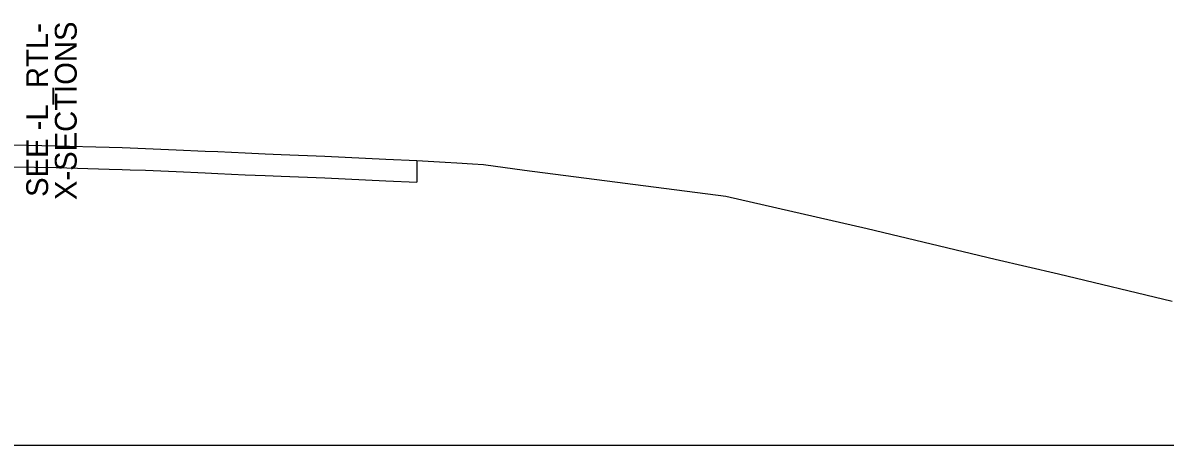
# Model space of a CAD drawing. Extents: x 2207892 to 2209721, y 61220 to 65449.
# Drawn here: x 2208142.1 to 2208194.4, y 62407.3 to 62426.6 of the extents above; entities that cross this region are included whole.
import ezdxf

# ---------------------------------------------------------------- set-up
doc = ezdxf.new("R2010")
doc.units = 0
for name, color, linetype in [('Exist DTM Breakline Cogo Elevation', 7, 'Continuous'), ('Exist DTM Drainline Cogo Comment', 7, 'Continuous'), ('Exist Roads EOP Other Cogo Elevation', 7, 'Continuous'), ('Exist Roads EOP Other Cogo Number', 7, 'Continuous')]:
    doc.layers.add(name, color=color, linetype=linetype)

msp = doc.modelspace()

# ---------------------------------------------------------------- linework, layer by layer
at = {"layer": 'Exist DTM Drainline Cogo Comment'}
for p, q in [((2208160.112, 62420.343), (2208160.112, 62419.343)), ((2208141.609, 62420.052), (2208143.592, 62420.017)), ((2208143.592, 62420.017), (2208146.02, 62419.943)), ((2208146.02, 62419.943), (2208146.612, 62419.927)), ((2208146.612, 62419.927), (2208146.978, 62419.916)), ((2208146.978, 62419.916), (2208147.679, 62419.892)), ((2208147.679, 62419.892), (2208149.08, 62419.828)), ((2208149.08, 62419.828), (2208150.418, 62419.772)), ((2208150.418, 62419.772), (2208150.987, 62419.747)), ((2208150.987, 62419.747), (2208152.25, 62419.689)), ((2208152.25, 62419.689), (2208153.158, 62419.648)), ((2208153.158, 62419.648), (2208153.901, 62419.618)), ((2208153.901, 62419.618), (2208155.899, 62419.538)), ((2208155.899, 62419.538), (2208158.68, 62419.403)), ((2208158.68, 62419.403), (2208160.112, 62419.343))]:
    msp.add_line(p, q, dxfattribs=at)
at = {"layer": 'Exist Roads EOP Other Cogo Elevation'}
msp.add_lwpolyline([(2208141.609, 62421.052), (2208143.592, 62421.017), (2208146.02, 62420.943), (2208146.612, 62420.927), (2208146.978, 62420.916), (2208147.679, 62420.892), (2208149.08, 62420.828), (2208150.418, 62420.772), (2208150.987, 62420.747), (2208152.25, 62420.689), (2208153.158, 62420.648), (2208153.901, 62420.618), (2208155.899, 62420.538), (2208158.68, 62420.403), (2208160.112, 62420.343), (2208161.403, 62420.261), (2208161.945, 62420.225), (2208162.65, 62420.179), (2208163.161, 62420.15), (2208165.039, 62419.9), (2208174.259, 62418.699), (2208180.733, 62417.224), (2208186.588, 62415.819), (2208189.484, 62415.159), (2208194.692, 62413.907)], dxfattribs=at)
at = {"layer": 'Exist Roads EOP Other Cogo Number'}
msp.add_line((2208118.174, 62407.31), (2208318.174, 62407.31), dxfattribs=at)

# ---------------------------------------------------------------- texts
at = {"layer": 'Exist DTM Breakline Cogo Elevation'}
for s, p in [('SEE -L_RTL- ', (2208143.222, 62418.673)), ('X-SECTIONS', (2208144.532, 62418.527))]:
    msp.add_text(s, height=1, rotation=90, dxfattribs=at).set_placement(p)

doc.saveas('drawing.dxf')
